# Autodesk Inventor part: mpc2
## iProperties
Shininess: 64.0
Length Units: 11269
Angle Units: 11279
Time Units: 11290
Mass Units: 11283
Length Display Precision: 3
Angle Display Precision: 2
Compacted: True
Part Number: mpc2
Document SubType Name: Modeling
Created: 2004-07
Designer: Peter
Manufacturer: Standard
Standards Organization: Custom
Density: 0.0
Volumn: 0.0
Area: 0.0
PropertySet Name: Model Information
Control State: 0
Master: False
Checked Out: False
Author: Peter
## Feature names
1. Extrusion1
